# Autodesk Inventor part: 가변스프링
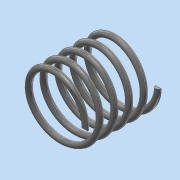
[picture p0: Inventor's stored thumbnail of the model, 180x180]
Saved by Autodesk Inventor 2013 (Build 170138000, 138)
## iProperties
Created: 2020-07
Part Number: 가변스프링
Material: 스테인리스강
Document SubType Name: Modeling
Designer: dgall
Density: 8.08 g/cm^3
Mass: 8.6262 g
Surface Area: 21.6415 cm^2
Volume: 1.0676 cm^3
Author: dgall
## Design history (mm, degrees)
sketch "스케치1"
  geometry: L1 (0, 0)-(0, 25.558); L2 (0, 25.558)-(11, 25.558); L3 (0, 0)-(11, 0); C1 r 1 at (11, 0)
  constraints: 6 end point, 2 parallel, 1 centre point, 1 coincident, 1 perpendicular, 1 vertical
  dimensions: "d0" = 25.55829 distance of L1.start L1.end (derived); "d1" = 22 diameter of L2.end L1; "d2" = 2 diameter of C1
feature "코일1" pitch "d3" = 10; turns "d5" = 5; dims "d4" = 25.55829 (= d0), "d6" = 0, angle "d7" = 90 deg, angle "d8" = 90 deg, "d9" = 0, "d10" = 0
node "작업 평면1"
node "작업 평면2"
feature "분할1"
feature "분할2"
node "솔리드1"
